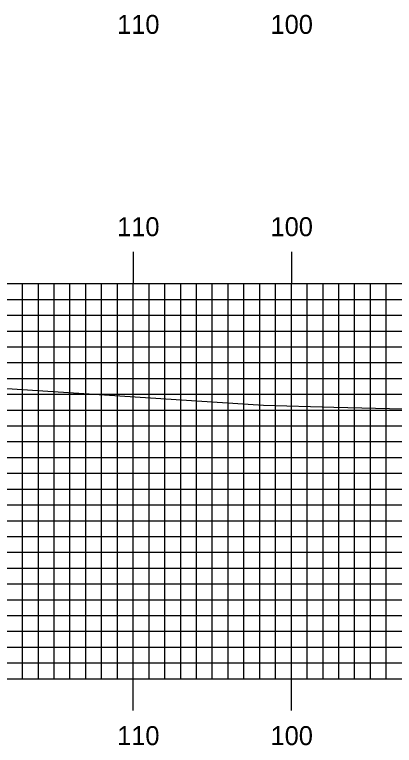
# Model space of a CAD drawing. Extents: x 1770842 to 1771185, y 442591 to 442811.
# Drawn here: x 1770890.05 to 1770914.07, y 442709.45 to 442755.68 of the extents above; entities that cross this region are included whole.
import ezdxf

# ---------------------------------------------------------------- set-up
doc = ezdxf.new("R2010")
doc.units = 0
for name, color, linetype in [('H_V ANNOTATION', 7, 'Continuous'), ('MAJOR', 7, 'Continuous'), ('MINOR', 7, 'Continuous'), ('S_Roadway_Centerline', 7, 'Continuous')]:
    doc.layers.add(name, color=color, linetype=linetype)

msp = doc.modelspace()

# ---------------------------------------------------------------- linework, layer by layer
at = {"layer": 'MAJOR'}
for p, q in [((1770897.554, 442740.669), (1770897.554, 442738.665)), ((1770907.554, 442740.669), (1770907.554, 442738.665)), ((1770867.554, 442738.665), (1771147.554, 442738.665)), ((1770867.554, 442738.665), (1771147.554, 442738.665)), ((1770897.554, 442713.665), (1770897.554, 442738.665)), ((1770907.554, 442713.665), (1770907.554, 442738.665)), ((1770867.554, 442733.665), (1771147.554, 442733.665)), ((1770867.554, 442728.665), (1771147.554, 442728.665)), ((1770867.554, 442723.665), (1771147.554, 442723.665)), ((1770867.554, 442718.665), (1771147.554, 442718.665)), ((1770867.554, 442713.665), (1771147.554, 442713.665)), ((1770867.554, 442713.665), (1771147.554, 442713.665)), ((1770897.554, 442711.661), (1770897.554, 442713.665)), ((1770907.554, 442711.661), (1770907.554, 442713.665))]:
    msp.add_line(p, q, dxfattribs=at)
at = {"layer": 'MINOR'}
for p, q in [((1770890.554, 442713.665), (1770890.554, 442738.665)), ((1770891.554, 442713.665), (1770891.554, 442738.665)), ((1770892.554, 442713.665), (1770892.554, 442738.665)), ((1770893.554, 442713.665), (1770893.554, 442738.665)), ((1770894.554, 442713.665), (1770894.554, 442738.665)), ((1770895.554, 442713.665), (1770895.554, 442738.665)), ((1770896.554, 442713.665), (1770896.554, 442738.665)), ((1770898.554, 442713.665), (1770898.554, 442738.665)), ((1770899.554, 442713.665), (1770899.554, 442738.665)), ((1770900.554, 442713.665), (1770900.554, 442738.665)), ((1770901.554, 442713.665), (1770901.554, 442738.665)), ((1770902.554, 442713.665), (1770902.554, 442738.665)), ((1770903.554, 442713.665), (1770903.554, 442738.665)), ((1770904.554, 442713.665), (1770904.554, 442738.665)), ((1770905.554, 442713.665), (1770905.554, 442738.665)), ((1770906.554, 442713.665), (1770906.554, 442738.665)), ((1770908.554, 442713.665), (1770908.554, 442738.665)), ((1770909.554, 442713.665), (1770909.554, 442738.665)), ((1770910.554, 442713.665), (1770910.554, 442738.665)), ((1770911.554, 442713.665), (1770911.554, 442738.665)), ((1770912.554, 442713.665), (1770912.554, 442738.665)), ((1770913.554, 442713.665), (1770913.554, 442738.665)), ((1770867.554, 442737.665), (1771147.554, 442737.665)), ((1770867.554, 442736.665), (1771147.554, 442736.665)), ((1770867.554, 442735.665), (1771147.554, 442735.665)), ((1770867.554, 442734.665), (1771147.554, 442734.665)), ((1770867.554, 442732.665), (1771147.554, 442732.665)), ((1770867.554, 442731.665), (1771147.554, 442731.665)), ((1770867.554, 442730.665), (1771147.554, 442730.665)), ((1770867.554, 442729.665), (1771147.554, 442729.665)), ((1770867.554, 442727.665), (1771147.554, 442727.665)), ((1770867.554, 442726.665), (1771147.554, 442726.665)), ((1770867.554, 442725.665), (1771147.554, 442725.665)), ((1770867.554, 442724.665), (1771147.554, 442724.665)), ((1770867.554, 442722.665), (1771147.554, 442722.665)), ((1770867.554, 442721.665), (1771147.554, 442721.665)), ((1770867.554, 442720.665), (1771147.554, 442720.665)), ((1770867.554, 442719.665), (1771147.554, 442719.665)), ((1770867.554, 442717.665), (1771147.554, 442717.665)), ((1770867.554, 442716.665), (1771147.554, 442716.665)), ((1770867.554, 442715.665), (1771147.554, 442715.665)), ((1770867.554, 442714.665), (1771147.554, 442714.665))]:
    msp.add_line(p, q, dxfattribs=at)
at = {"layer": 'S_Roadway_Centerline'}
msp.add_lwpolyline([(1770867.554, 442732.926), (1770875.047, 442732.521), (1770885.347, 442732.269), (1770888.578, 442732.094), (1770905.792, 442730.965), (1770910.229, 442730.845), (1770918.156, 442730.666), (1770922.756, 442730.55), (1770925.566, 442730.483), (1770933.687, 442729.93), (1770944.441, 442729.295)], dxfattribs=at)

# ---------------------------------------------------------------- texts
at = {"layer": 'H_V ANNOTATION'}
for s, p in [('110', (1770896.538, 442754.465)), ('100', (1770906.238, 442754.465)), ('110', (1770896.538, 442741.665)), ('100', (1770906.238, 442741.665)), ('110', (1770896.538, 442709.465)), ('100', (1770906.238, 442709.465))]:
    msp.add_text(s, height=1.2, dxfattribs=at).set_placement(p)

doc.saveas('drawing.dxf')
